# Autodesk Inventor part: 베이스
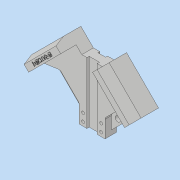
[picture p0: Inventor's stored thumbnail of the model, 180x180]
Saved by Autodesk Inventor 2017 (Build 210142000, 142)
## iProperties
Part Number: 베이스
Material: 일반
Document SubType Name: Modeling
Designer: 222
Density: 1 g/cm^3
Appearance: 기본값
Mass: 211.693 g
Surface Area: 407.229 cm^2
Volume: 211.693 cm^3
Author: 222
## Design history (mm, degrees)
sketch "스케치1"
  geometry: L1 (-84.853, 0)-(0, 84.853); L2 (0, 84.853)-(84.853, 0); L3 (84.853, 0)-(0, -84.853); L4 (0, -84.853)-(-84.853, 0); 1 further point
  constraints: 8 end point, 2 horizontal alignment, 2 parallel, 2 vertical alignment, 1 perpendicular
  dimensions: "d0" = 120 distance of L1.end L2.end
extrude "돌출1" new body sketch "스케치1" distance "d1" = 42; taper "d2" = 0 deg
sketch "스케치2"
  geometry: L1 (0, 84.853)-(-84.853, 0) reference; L2 (-84.853, 0)-(0, -84.853) reference; L3 (0, -84.853)-(84.853, 0) reference; L4 (84.853, 0)-(0, 84.853) reference; L5 (-74.246, -10.607)-(0, 63.64); L6 (0, 63.64)-(74.246, -10.607); 1 further point
  constraints: 4 end point, 2 point on line, 1 other
  dimensions: "d3" = 15 distance between parallel lines of L1 L5
extrude "돌출2" cut sketch "스케치2" distance "d4" = 24; taper "d5" = 0 deg
sketch "스케치3"
  geometry: L1 (-35.355, 49.497)-(-16.005, 30.147); L2 (-16.005, 30.147)-(16.005, 30.147); L3 (16.005, 30.147)-(35.355, 49.497); L4 (-74.246, -10.607)-(-49.497, -7.071); L5 (0, -84.853)-(-84.853, 0) reference; L6 (-20, -36.569)-(-20, -64.853); L7 (20, -64.853)-(20, -36.569); L8 (20, -36.569)-(49.497, -7.071); L9 (49.497, -7.071)-(74.246, -10.607); L10 (74.246, -10.607)-(0, -84.853) reference; L11 (-74.246, -10.607)-(0, 63.64) reference; L12 (0, 63.64)-(74.246, -10.607) reference; L13 (74.246, -10.607)-(84.853, 0) reference; L14 (84.853, 0)-(0, 84.853) reference; L15 (0, 84.853)-(-84.853, 0) reference; L16 (-84.853, 0)-(-74.246, -10.607) reference; L17 (74.246, -10.607)-(0, -84.853) reference; L18 (0, 63.64)-(74.246, -10.607) reference; L19 (-74.246, -10.607)-(0, 63.64) reference; L20 (0, -84.853)-(-74.246, -10.607) reference; L21 (-49.497, -7.071)-(-20, -36.569); L22 (-20, -64.853)-(20, -64.853); 1 further point
  constraints: 20 end point, 6 point on line, 3 horizontal alignment, 2 horizontal, 2 parallel, 2 perpendicular, 2 vertical
  dimensions: "d6" = 50 distance of L14.end L1.start; "d7" = 50 distance of L3.end L14.end; "d8" = 20 horizontal distance of L6.end L5.start; "d9" = 20 distance from line of L20 L4.end; "d10" = 30 distance from line of L15 L4.end; "d11" = 95 distance between parallel lines of L2 L22
extrude "돌출3" cut sketch "스케치3" stored distance "d14" = 24; taper "d15" = 0 deg
sketch "스케치4"
  geometry: L1 (16.005, 30.147)-(-16.005, 30.147) reference; L2 (-20, -64.853)-(20, -64.853) reference; L3 (-8, 30.147)-(-8, -64.853); L4 (20, -64.853)-(-20, -64.853) reference; L5 (8, -64.853)-(8, 30.147); 1 further point
  constraints: 4 end point, 4 point on line, 1 perpendicular, 1 vertical
  dimensions: "d16" = 16 distance between parallel lines of L5 L3; "d17" = 8 distance from line of L5 point (0, 0)
extrude "돌출4" cut sketch "스케치4" distance "d18" = 3.5; taper "d19" = 0 deg
fillet "모깎기1" dims "d20" = 5
sketch "스케치5"
  geometry: L1 (-8, -64.853)-(-8, 30.147) reference; L2 (-8, 30.147)-(-16.005, 30.147) reference; L3 (-16.005, 30.147)-(-24.749, 38.891) reference; L4 (-74.246, -10.607)-(-24.749, 38.891) reference; L5 (-74.246, -10.607)-(-51.972, -7.425) reference; L6 (-47.73, -8.839)-(-21.464, -35.104) reference; L7 (-20, -38.64)-(-20, -64.853) reference; L8 (-20, -64.853)-(-8, -64.853) reference; L9 (8, 30.147)-(8, -64.853) reference; L10 (8, -64.853)-(20, -64.853) reference; L11 (20, -64.853)-(20, -38.64) reference; L12 (21.464, -35.104)-(47.73, -8.839) reference; L13 (51.972, -7.425)-(74.246, -10.607) reference; L14 (24.749, 38.891)-(74.246, -10.607) reference; L15 (24.749, 38.891)-(16.005, 30.147) reference; L16 (16.005, 30.147)-(8, 30.147) reference; L17 (-68.059, -9.723)-(-20, -57.782); L18 (20, -57.782)-(68.059, -9.723); L19 (-74.246, -10.607)-(-51.972, -7.425) reference; L20 (-20, -38.64)-(-20, -64.853) reference; L21 (20, -64.853)-(20, -38.64) reference; L22 (51.972, -7.425)-(74.246, -10.607) reference; L23 (-47.73, -8.839)-(-21.464, -35.104) reference; L24 (21.464, -35.104)-(47.73, -8.839) reference; L25 (74.246, -10.607)-(84.853, 0) reference; L26 (-84.853, 0)-(-74.246, -10.607) reference; A1 r 5 centre (-51.265, -12.374) between (-47.73, -8.839) and (-51.972, -7.425) reference; A2 r 5 centre (-25, -38.64) between (-20, -38.64) and (-21.464, -35.104) reference; A3 r 5 centre (25, -38.64) between (21.464, -35.104) and (20, -38.64) reference; A4 r 5 centre (51.265, -12.374) between (51.972, -7.425) and (47.73, -8.839) reference; 1 further point
  constraints: 4 end point, 4 point on line, 2 parallel
  dimensions: "d21" = 5 distance between parallel lines of L25 L18; "d22" = 5 distance between parallel lines of L26 L17
extrude "돌출5" join sketch "스케치5" distance "d23" = 8; taper "d24" = 0 deg
sketch "스케치6"
  geometry: L1 (-49.497, -18.385)-(-29.698, -38.184); L2 (-52.326, -21.213)-(-32.527, -41.012); L3 (-26.87, -35.355)-(-46.669, -15.556); L4 (49.497, -18.385)-(29.698, -38.184); L5 (46.669, -15.556)-(26.87, -35.355); L6 (32.527, -41.012)-(52.326, -21.213); L7 (-84.853, 0)-(-74.246, -10.607) reference; L8 (-35.355, 49.497)-(-84.853, 0) reference; L9 (84.853, 0)-(35.355, 49.497) reference; A1 r 4 centre (-49.497, -18.385) between (-46.669, -15.556) and (-52.326, -21.213); A2 r 4 centre (-29.698, -38.184) between (-32.527, -41.012) and (-26.87, -35.355); A3 r 4 centre (49.497, -18.385) between (52.326, -21.213) and (46.669, -15.556); A4 r 4 centre (29.698, -38.184) between (26.87, -35.355) and (32.527, -41.012); 3 further points
  constraints: 16 end point, 8 point on circle, 8 tangent, 4 centre point, 3 horizontal alignment, 2 midpoint, 2 parallel, 1 perpendicular
  dimensions: "d25" = 28 distance of L1.start L1.end; "d26" = 8 diameter of A2; "d27" = 28 distance of L4.start L4.end; "d28" = 8 diameter of A4; "d29" = 12 distance from line of point (-39.598, -28.284) L7; "d30" = 38 distance from line of L1.start L8; "d31" = 38 distance from line of L4.start L9
extrude "돌출6" cut sketch "스케치6" stored distance "d32" = 8; taper "d33" = 0 deg
sketch "스케치7"
  geometry: L1 (-20, -64.853)-(20, -64.853) reference; L2 (16.005, 30.147)-(-16.005, 30.147) reference; L3 (-6, 30.147)-(-6, -64.853); L4 (6, 30.147)-(6, -64.853); 5 further points
  constraints: 4 end point, 4 point on line, 2 horizontal alignment, 2 vertical alignment, 1 vertical
  dimensions: "d34" = 28 distance of point (14, -58.853) point (-14, -58.853); "d35" = 6 distance from line of point (14, -58.853) L1; "d36" = 12 distance of point (14, -46.853) point (14, -58.853); "d37" = 14 horizontal distance of point (0, 0) point (14, -58.853); "d45" = 12 distance between parallel lines of L4 L3; "d46" = 6 distance from line of L4 point (0, 0)
hole "구멍1" sketch "스케치7" diameter "d38" = 4.5; stored, may be unused: countersink angle "d42" = 90 deg, drill point angle "d44" = 118 deg; dims "d39" = 6, "d40" = 8, "d41" = 10, "d43" = 8
extrude "돌출7" cut sketch "스케치7" distance "d47" = 3; taper "d48" = 0 deg
chamfer "모따기1" distance "d49" = 5; stored, may be unused: second distance "d50" = 15, angle "d51" = 45 deg
chamfer "모따기2" distance "d52" = 5; stored, may be unused: second distance "d53" = 15, angle "d54" = 45 deg
sketch "스케치8"
  geometry: L1 (-74.246, -10.607)-(-24.749, 38.891) reference; L2 (-31.82, 45.962)-(-35.355, 49.497) reference; 2 further points
  constraints: 1 other
  dimensions: "d55" = 5 distance from line of L1 point (-53.033, 17.678); "d56" = 35 distance from line of L2 point (-53.033, 17.678)
feature "엠보싱1" sketch "스케치8" dims "d0" = 120, "d57" = 0.5, "d58" = 0
node "솔리드1"
node "투영된 루프1"
node "투영된 루프2"
node "투영된 루프3"
node "투영된 루프4"
node "투영된 루프5"
